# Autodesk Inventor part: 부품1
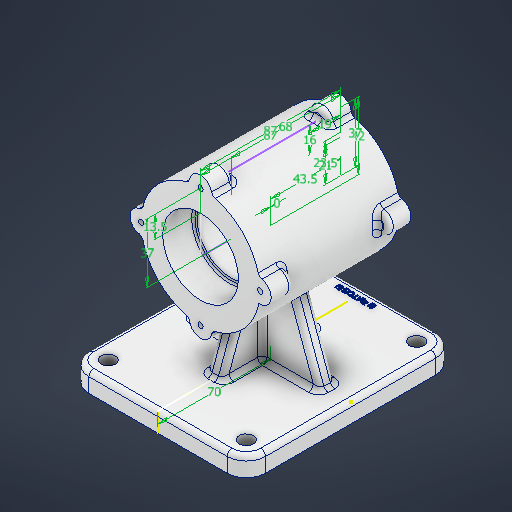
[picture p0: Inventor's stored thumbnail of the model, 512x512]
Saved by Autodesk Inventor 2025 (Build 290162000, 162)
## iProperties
Created: 2025-08
Part Number: 부품1
Material: 알루미늄 6061
Document SubType Name: Modeling
Designer: infra023
Density: 2.7 g/cm^3
Appearance: 알루미늄 - 평지
Mass: 1222.85 g
Surface Area: 802.911 cm^2
Volume: 452.907 cm^3
Author: infra023
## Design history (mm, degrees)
sketch "스케치1"
  geometry: L1 (55, 65)-(-55, 65); L2 (-55, 65)-(-55, -65); L3 (-55, -65)-(55, -65); L4 (55, -65)-(55, 65); 3 further points
  constraints: 8 end point, 2 midpoint, 2 parallel, 1 horizontal, 1 horizontal alignment, 1 perpendicular, 1 vertical alignment
  dimensions: "d0" = 130 distance of L3.end L1.start; "d1" = 110 distance of L2.end L3.end
extrude "돌출1" new body sketch "스케치1" distance "d2" = 12; taper "d3" = 0 deg
fillet "모깎기1" dims "d4" = 12
sketch "스케치2"
  geometry: L1 (43, 53)-(-43, 53); L2 (-43, 53)-(-43, -53); L3 (-43, -53)-(43, -53); L4 (43, -53)-(43, 53); 3 further points
  constraints: 8 end point, 2 midpoint, 2 parallel, 1 horizontal, 1 horizontal alignment, 1 perpendicular, 1 vertical alignment
  dimensions: "d5" = 106 distance of L1.end L2.end; "d6" = 86 distance of L2.end L3.end
hole "구멍1" sketch "스케치2" at (43, 53), (43, -53), (-43, -53), (-43, 53) diameter "d7" = 9; stored, may be unused: countersink angle "d11" = 90 deg, drill point angle "d13" = 118 deg; dims "d8" = 6, "d9" = 4, "d10" = 2, "d12" = 8
sketch "스케치3"
  geometry: L1 (-12, -53)-(-12, 53) reference; L2 (70, -5)-(70, -48.5); L3 (70, -48.5)-(107, -48.5); L4 (107, -48.5)-(107, 38.5); L5 (107, 38.5)-(70, 38.5); L6 (70, -5)-(70, 38.5); L7 (70, -48.5)-(91, -48.5); L8 (91, -29.5)-(91, 19.5); L9 (70, -48.5)-(93.5, -48.5); L10 (93.5, -48.5)-(93.5, -29.5); L11 (93.5, -29.5)-(70, -29.5); L12 (93.5, 38.5)-(93.5, 19.5); L13 (93.5, 19.5)-(70, 19.5); L14 (-12, 65)-(0, 65) reference; L15 (0, 65)-(0, -5); L16 (0, -53)-(0, 53) reference; L17 (0, -5)-(65, -5); 2 further points
  constraints: 28 end point, 6 perpendicular, 6 point on line, 3 parallel, 1 vertical
  dimensions: "d15" = 43.5 distance of L2.start L2.end; "d16" = 37 distance of L2.end L3.end; "d17" = 87 distance of L3.end L4.end; "d18" = 21 distance of L2.end L7.end; "d19" = 23.5 distance of L2.end L9.end; "d20" = 19 distance of L9.end L10.end; "d21" = 16 distance between parallel lines of L4 L8; "d112" = 70 distance of L14.end L15.end; "d114" = 13.5 distance between parallel lines of L12 L4; "d115" = 68 distance between parallel lines of L13 L3; "d117" = 87 distance from line of L12.start L3; "d118" = 37 distance from line of L13.end L4; "d119" = 42 distance from line of L17.end L4; "d120" = 0 vertical distance of L2.start L17.end
revolve "회전1" sketch "스케치3" stored, may be unused: angle "d22" = 90 deg
sketch "스케치4"
  geometry: L1 (0, 0)-(0, 37); L2 (0, 0)-(-37, 0); L3 (0, 0)-(37, 0); L4 (0, 0)-(0, -37); C1 r 21 at (0, 0) reference; C2 r 7 at (37, 0); C3 r 7 at (-37, 0); C4 r 7 at (0, 37); C5 r 7 at (0, -37); A1 r 37 centre (0, 0) between (0, 37) and (-37, 0) reference; 3 further points
  constraints: 8 end point, 4 centre point, 4 coincident, 4 point on circle, 2 horizontal, 2 vertical
  dimensions: "d23" = 14 diameter of C2; "d24" = 14 diameter of C3; "d25" = 14 diameter of C4; "d26" = 14 diameter of C5
sketch "스케치5"
  geometry: C1 r 7 at (0, 37) reference; C2 r 7 at (-37, 0) reference; C3 r 7 at (37, 0) reference; C4 r 7 at (0, -37) reference; 1 further point
extrude "돌출2" join sketch "스케치4" distance "d27" = 14; taper "d28" = 0 deg
extrude "돌출3" join sketch "스케치5" distance "d29" = 14; taper "d30" = 0 deg
fillet "모깎기2" dims "d31" = 3
fillet "모깎기3" dims "d32" = 3
fillet "모깎기4" dims "d33" = 3
sketch "스케치6"
  geometry: L1 (-37, -37)-(0, -37); C1 r 7 at (-37, -37); A1 r 7 centre (-37, -37) between (-38.239, -30.111) and (-38.239, -43.889) reference; A2 r 40 centre (0, -37) between (-39.905, -34.251) and (-39.905, -39.749) reference; 3 further points
  constraints: 2 end point, 1 centre point, 1 coincident, 1 concentric, 1 horizontal
extrude "돌출4" join sketch "스케치6" distance "d34" = 14; taper "d35" = 0 deg
fillet "모깎기5" dims "d36" = 3
sketch "스케치7"
  geometry: L1 (0, 37)-(-37, 37); L2 (0, 37)-(0, 74); L3 (0, 37)-(37, 37); L4 (0, 37)-(0, 0); C1 r 23.5 at (0, 37) reference; C2 r 37 at (0, 37); 1 further point
  constraints: 8 end point, 2 horizontal, 2 vertical, 1 centre point, 1 coincident
  dimensions: "d37" = 74 diameter of C2; "d38" = 37 distance of L1.start L1.end; "d39" = 37 distance of L1.start L2.end; "d40" = 37 distance of L1.start L3.end; "d41" = 37 distance of L1.start L4.end
hole "구멍2" sketch "스케치7" at (0, 74), (-37, 37), (37, 37), (0, 0) diameter "d42" = 3.242; stored, may be unused: countersink angle "d46" = 90 deg, drill point angle "d48" = 118 deg; dims "d43" = 8, "d44" = 4, "d45" = 2, "d47" = 10
sketch "스케치8"
  geometry: C1 r 1.621 at (0, 0) reference; C2 r 1.621 at (37, -37) reference; C3 r 1.621 at (-37, -37) reference; C4 r 1.621 at (0, -74) reference; 1 further point
hole "구멍3" sketch "스케치8" at (0, 0), (-37, -37), (37, -37), (0, -74) diameter "d49" = 3.242; stored, may be unused: countersink angle "d53" = 90 deg, drill point angle "d55" = 118 deg; dims "d50" = 8, "d51" = 4, "d52" = 2, "d54" = 10
sketch "스케치9"
  geometry: L1 (0, 0)-(0, 30); L2 (0, -53)-(0, 53) reference; L3 (0, 0)-(0, -30); L4 (0, 30)-(40, 15.441); L5 (0, 30)-(53.209, 30); L6 (0, -30)-(33, -17.989); L7 (0, -30)-(44.695, -30); L8 (0, 0)-(63, 0); L9 (33, -31.5)-(33, 21.5) reference; L10 (33, -5)-(33, 22); L11 (33, -5)-(33, -22.357); L12 (33, -17.989)-(40, -15.441); L13 (40, -15.441)-(40, 15.441); 1 further point
  constraints: 22 end point, 5 point on line, 3 horizontal, 1 midpoint, 1 vertical
  dimensions: "d56" = 30 distance of L1.start L1.end; "d57" = 30 distance of L1.start L3.end; "d58" = 20 deg angle of L4 L5; "d59" = 20 deg angle of L7 L6; "d71" = 70 deg angle of L12 L9; "d72" = 7 distance between parallel lines of L13 L9; "d73" = 30 distance from line of L8.end L9; "d74" = 37.57735 distance from line of L10.end L12; "d75" = 4.10424 distance from line of L11.end L12
sketch "스케치10"
  geometry: L1 (-43, -3)-(-55, -3) reference; L2 (-55, -3)-(-41, -3); L3 (43, -3)-(-43, -3) reference; L4 (-41, -3)-(-41, 0); L5 (-43, 0)-(-41, 0); L6 (-47.5, 0)-(-38.5, 0) reference; L7 (-41, 0)-(-24.257, 46); L8 (-41, 0)-(7.952, 0); L9 (43, -12)-(-43, -12) reference; L10 (0, 0)-(0, 49); L11 (55, -12)-(55, 0); L12 (55, -3)-(55, -12) reference; L13 (55, 0)-(41, 0); L14 (-41, 0)-(0, 0); L15 (41, 0)-(24.257, 46); 1 further point
  constraints: 20 end point, 2 collinear, 2 point on line, 1 equal length, 1 horizontal, 1 parallel, 1 perpendicular, 1 symmetric about line, 1 vertical, 1 vertical alignment, 1 other
  dimensions: "d62" = 14 distance of L1.end L2.end; "d63" = 70 deg angle of L8 L7; "d82" = 12 distance of L11.start L11.end; "d83" = 14 distance of L11.end L13.end; "d85" = 7.95218 distance from line of L8.end L10; "d86" = 20 deg angle of L10 L15
extrude "돌출6" join sketch "스케치9" stored distance "d76" = 10; taper "d77" = 0 deg
feature "리브2" dims "d87" = 1, "d88" = 10, "d89" = 0, "d90" = 0, "d91" = 1, "d92" = 1
sketch "스케치11"
  geometry: L1 (55, -3)-(55, -12) reference; L2 (55, -12)-(55, 0); L3 (-43, 0)-(43, 0) reference; L4 (41, 0)-(23.529, 48); 1 further point
  constraints: 4 end point, 1 collinear, 1 point on line
  dimensions: "d93" = 12 distance of L1.end L2.end; "d94" = 14 distance of L2.end L4.start; "d96" = 20 deg angle of L1 L4; "d97" = 31.47057 distance from line of L4.end L1
feature "리브3" sketch "스케치11" dims "d98" = 1, "d99" = 10, "d100" = 0, "d101" = 0, "d102" = 1, "d103" = 1
fillet "모깎기10" dims "d104" = 3
fillet "모깎기12" dims "d106" = 3
fillet "모깎기13" dims "d107" = 3
sketch "스케치12" dims "d0" = 130, "d1" = 110
  geometry: L1 (12.123, 56.285)-(-12.123, 56.285); L2 (-12.123, 56.285)-(-12.123, 59.715); L3 (-12.123, 59.715)-(12.123, 59.715); L4 (12.123, 59.715)-(12.123, 56.285); L5 (0, 0)-(0, 58); 2 further points
  constraints: 2 end point, 2 midpoint, 1 horizontal alignment, 1 vertical, 1 vertical alignment, 2 other
  dimensions: "d108" = 58 distance of L5.start L5.end
feature "엠보싱1" sketch "스케치12" dims "d0" = 130, "d1" = 110, "d109" = 0.5, "d110" = 0
fillet "모깎기14" dims "d111" = 1
sketch "스케치13"
  geometry: 1 further point
node "솔리드1"
feature "A9D066F2-1C7D-4E18-AEED-F7BC21143FA4" dims "d7" = 9, "d8" = 6, "d9" = 4, "d10" = 2, "d11" = 90 deg, "d12" = 8, "d13" = 118 deg
